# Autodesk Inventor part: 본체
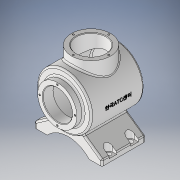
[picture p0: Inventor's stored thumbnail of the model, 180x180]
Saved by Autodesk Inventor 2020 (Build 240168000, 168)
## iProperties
Created: 2023-12
Part Number: 본체
Material: 일반
Document SubType Name: Modeling
Designer: 1강의실14
Density: 1 g/cm^3
Appearance: 기본값
Author: 1강의실14
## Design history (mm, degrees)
sketch "스케치2" dims "d7" = 226
  geometry: L1 (0, -99.2)-(0, 217.2) reference; L2 (0, 54)-(50, 54); L3 (50, 54)-(50, -54); L4 (50, -54)-(0, -54); 4 further points
  constraints: 6 end point, 2 point on line, 1 horizontal, 1 horizontal alignment, 1 midpoint, 1 perpendicular, 1 vertical alignment, 3 other
  dimensions: "d3" = 50 distance of L2.start L2.end; "d4" = 108 distance of L2.end L3.end; "d5" = 50 distance of L3.end L4.end
revolve "회전1" sketch "스케치2" stored, may be unused: angle "d6" = 90 deg
feature "쉘1" dims "d8" = 7
sketch "스케치5"
  geometry: C1 r 36 at (0, 0); 1 further point
  constraints: 1 centre point, 1 coincident
  dimensions: "d15" = 72 diameter of C1
extrude "돌출3" join sketch "스케치5" distance "d16" = 12; taper "d17" = 0 deg
node "작업 평면1"
sketch "스케치4"
  geometry: L1 (36, 66)-(-36, 66) reference; C1 r 36 at (0, 4); 1 further point
  constraints: 1 centre point, 1 vertical alignment
  dimensions: "d13" = 72 diameter of C1; "d18" = 62 distance from line of C1.centre L1
extrude "돌출4" join sketch "스케치4" stored distance "d19" = 12; taper "d20" = 0 deg
sketch "스케치6"
  geometry: C1 r 36 at (0, 0) reference; C2 r 27 at (0, 0); 1 further point
  constraints: 1 centre point, 1 coincident
  dimensions: "d21" = 54 diameter of C2
extrude "돌출5" cut sketch "스케치6" distance "d22" = 46; taper "d23" = 0 deg
sketch "스케치7"
  geometry: C1 r 27 at (0, 0); 1 further point
  constraints: 1 centre point, 1 coincident
  dimensions: "d24" = 54 diameter of C1
extrude "돌출6" cut sketch "스케치7" distance "d25" = 46; taper "d26" = 0 deg
sketch "스케치8"
  geometry: L1 (0, -73)-(0, 88) reference; L2 (26.694, -42.278)-(62, -67); L3 (62, -67)-(62, -77); L4 (62, -77)-(-62, -77); L5 (-62, -77)-(-62, -67); L6 (-62, -67)-(-26.694, -42.278); A1 r 50 centre (0, 0) between (26.694, -42.278) and (-26.694, -42.278) reference; 2 further points
  constraints: 10 end point, 2 perpendicular, 2 point on circle, 1 midpoint, 1 vertical, 1 vertical alignment
  dimensions: "d27" = 10 distance of L2.end L3.end; "d28" = 124 distance of L3.end L4.end; "d29" = 10 distance of L4.end L5.end; "d30" = 55 deg angle of L3 L2; "d31" = 55 deg angle of L6 L5; "d32" = 77 distance from line of L4 point (0, 0)
extrude "돌출7" join sketch "스케치8" distance "d33" = 46; taper "d34" = 0 deg; dims "d82" = 34, "d83" = 0
sketch "스케치9"
  geometry: L1 (62, -77)-(-62, -77) reference; A1 r 52.096 centre (0, -112.096) between (38.5, -77) and (-38.5, -77); 2 further points
  constraints: 3 point on circle, 2 point on line, 1 centre point, 1 vertical alignment
  dimensions: "d35" = 77 distance of A1.end A1.start; "d36" = 17 distance from line of L1 point (0, -60)
extrude "돌출8" cut sketch "스케치9" distance "d37" = 80; taper "d38" = 0 deg
sketch "스케치10"
  geometry: L1 (0, 0)-(0, 32.5)
  constraints: 2 end point, 1 vertical
  dimensions: "d39" = 32.5 distance of L1.start L1.end
hole "구멍1" sketch "스케치10" at (0, 32.5) diameter "d40" = 3.242; stored, may be unused: countersink angle "d44" = 90 deg, drill point angle "d46" = 118 deg; dims "d41" = 8, "d42" = 4, "d43" = 2, "d45" = 10
sketch "스케치11"
  geometry: L1 (0, 0)-(-32.5, 0); C1 r 36 at (0, 0) reference; 1 further point
  constraints: 2 end point, 1 horizontal
  dimensions: "d50" = 32.5 distance of L1.start L1.end
hole "구멍2" sketch "스케치11" at (-32.5, 0) diameter "d51" = 3.242; stored, may be unused: countersink angle "d55" = 90 deg, drill point angle "d57" = 118 deg; dims "d52" = 8, "d53" = 4, "d54" = 2, "d56" = 10
fillet "모깎기1" dims "d69" = 3
fillet "모깎기2" dims "d70" = 3
fillet "모깎기3" dims "d71" = 3
fillet "모깎기5" dims "d74" = 3
chamfer "모따기1" distance "d75" = 1; stored, may be unused: second distance "d76" = 2, angle "d77" = 45 deg
node "작업 평면2"
sketch "스케치15"
  geometry: L1 (36, 66)-(-36, 66) reference; 2 further points
  constraints: 1 vertical alignment, 1 other
  dimensions: "d79" = 62 distance from line of L1 point (0, 4)
feature "엠보싱1" sketch "스케치15" dims "d3" = 50, "d80" = 0.5, "d81" = 0
fillet "모깎기6" dims "d101" = 3
sketch "스케치16"
  geometry: L1 (0, 0)-(0, 80) reference; L2 (-23.5, 80)-(0, 80) reference; C1 r 4.5 at (-8, 60); 1 further point
  constraints: 1 centre point
  dimensions: "d84" = 9 diameter of C1; "d85" = 8 distance from line of L1 C1.centre; "d86" = 20 distance from line of L2 C1.centre
extrude "돌출11" cut sketch "스케치16" distance "d87" = 6; taper "d88" = 0 deg
sketch "스케치17"
  geometry: L1 (15, 0)-(0, 0); L2 (15, 7)-(0, 7); L3 (0, -7)-(15, -7); C1 r 4.5 at (0, 0) reference; A1 r 7 centre (15, 0) between (15, -7) and (15, 7); A2 r 7 centre (0, 0) between (0, 7) and (0, -7); 2 further points
  constraints: 8 end point, 4 point on circle, 4 tangent, 2 centre point, 1 horizontal, 1 midpoint, 1 parallel
  dimensions: "d89" = 14 diameter of A2; "d90" = 15 distance of L2.start L2.end
extrude "돌출12" cut sketch "스케치17" distance "d91" = 20.75; taper "d92" = 0 deg
sketch "스케치18"
  geometry: C1 r 4.5 at (-8, 60) reference; C2 r 4.5 at (-8, 20); 1 further point
  constraints: 1 centre point, 1 vertical alignment
  dimensions: "d93" = 9 diameter of C2; "d94" = 40 distance of C2.centre C1.centre
extrude "돌출13" cut sketch "스케치18" distance "d95" = 6; taper "d96" = 0 deg
sketch "스케치19"
  geometry: L1 (15, 0)-(0, 0); L2 (15, 7)-(0, 7); L3 (0, -7)-(15, -7); C1 r 4.5 at (0, 0) reference; A1 r 7 centre (15, 0) between (15, -7) and (15, 7); A2 r 7 centre (0, 0) between (0, 7) and (0, -7); 2 further points
  constraints: 8 end point, 4 point on circle, 4 tangent, 2 centre point, 1 horizontal, 1 midpoint, 1 parallel
  dimensions: "d97" = 14 diameter of A2; "d98" = 15 distance of L2.start L2.end
extrude "돌출14" cut sketch "스케치19" distance "d99" = 20; taper "d100" = 0 deg
node "솔리드2"
pattern_circular "원형 패턴1" dims angle "d48" = 360 deg
pattern_circular "원형 패턴2" dims angle "d59" = 360 deg
mirror "미러3"
mirror "미러4"
feature "A9D066F2-1C7D-4E18-AEED-F7BC21143FA4" dims "d40" = 3.242, "d41" = 8, "d42" = 4, "d43" = 2, "d44" = 90 deg, "d45" = 10, "d46" = 118 deg
other parameters: "d12" = 65, "d78" = 58.25
